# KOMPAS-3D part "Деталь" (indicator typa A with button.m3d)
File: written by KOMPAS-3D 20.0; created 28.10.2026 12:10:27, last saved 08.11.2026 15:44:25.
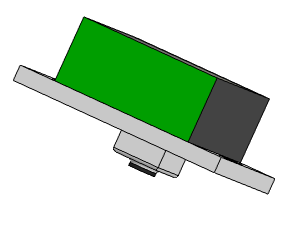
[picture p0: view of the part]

Document properties: Полное имя файла: D:\myProjects\Progect_esp32\box_compas\переключатели и кнопки\indicator typa A with button.m3d

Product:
- Part/product: Деталь
    Масса: 0.005156

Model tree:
1. Эскиз:1
2. Элемент выдавливания:1
     Расстояние 1 = 1.2
3. Эскиз:2  (with: Элемент выдавливания:1)
4. Элемент выдавливания:2
     Расстояние 2 = 1.2
5. Эскиз:3  (with: Элемент выдавливания:1)
6. Элемент выдавливания:3
     Расстояние 1 = 5
7. Эскиз:4  (with: Элемент выдавливания:1)
8. Элемент выдавливания:4
     Расстояние 1 = 1.6
9. Эскиз:5  (with: Элемент выдавливания:4)
10. Элемент выдавливания:5
     Расстояние 1 = 0.5
11. Скругление:1  (with: Элемент выдавливания:4)
     Радиус = 0.25
12. Эскиз:6  (with: Элемент выдавливания:1, Элемент выдавливания:3)
13. Элемент выдавливания:6
     Расстояние 2 = 0.1
14. Эскиз:7  (with: Элемент выдавливания:1, Элемент выдавливания:3)
15. Элемент выдавливания:7
     Расстояние 2 = 0.1

Referenced files in D:\RicWork\Project-EPS32\box_compas\переключатели и кнопки\: indicator typa A with button bottom.png, indicator typa A with button up.png
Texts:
  indicator typa A with button bottom.png
  indicator typa A with button up.png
